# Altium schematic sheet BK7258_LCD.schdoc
size 335 x 193 mm
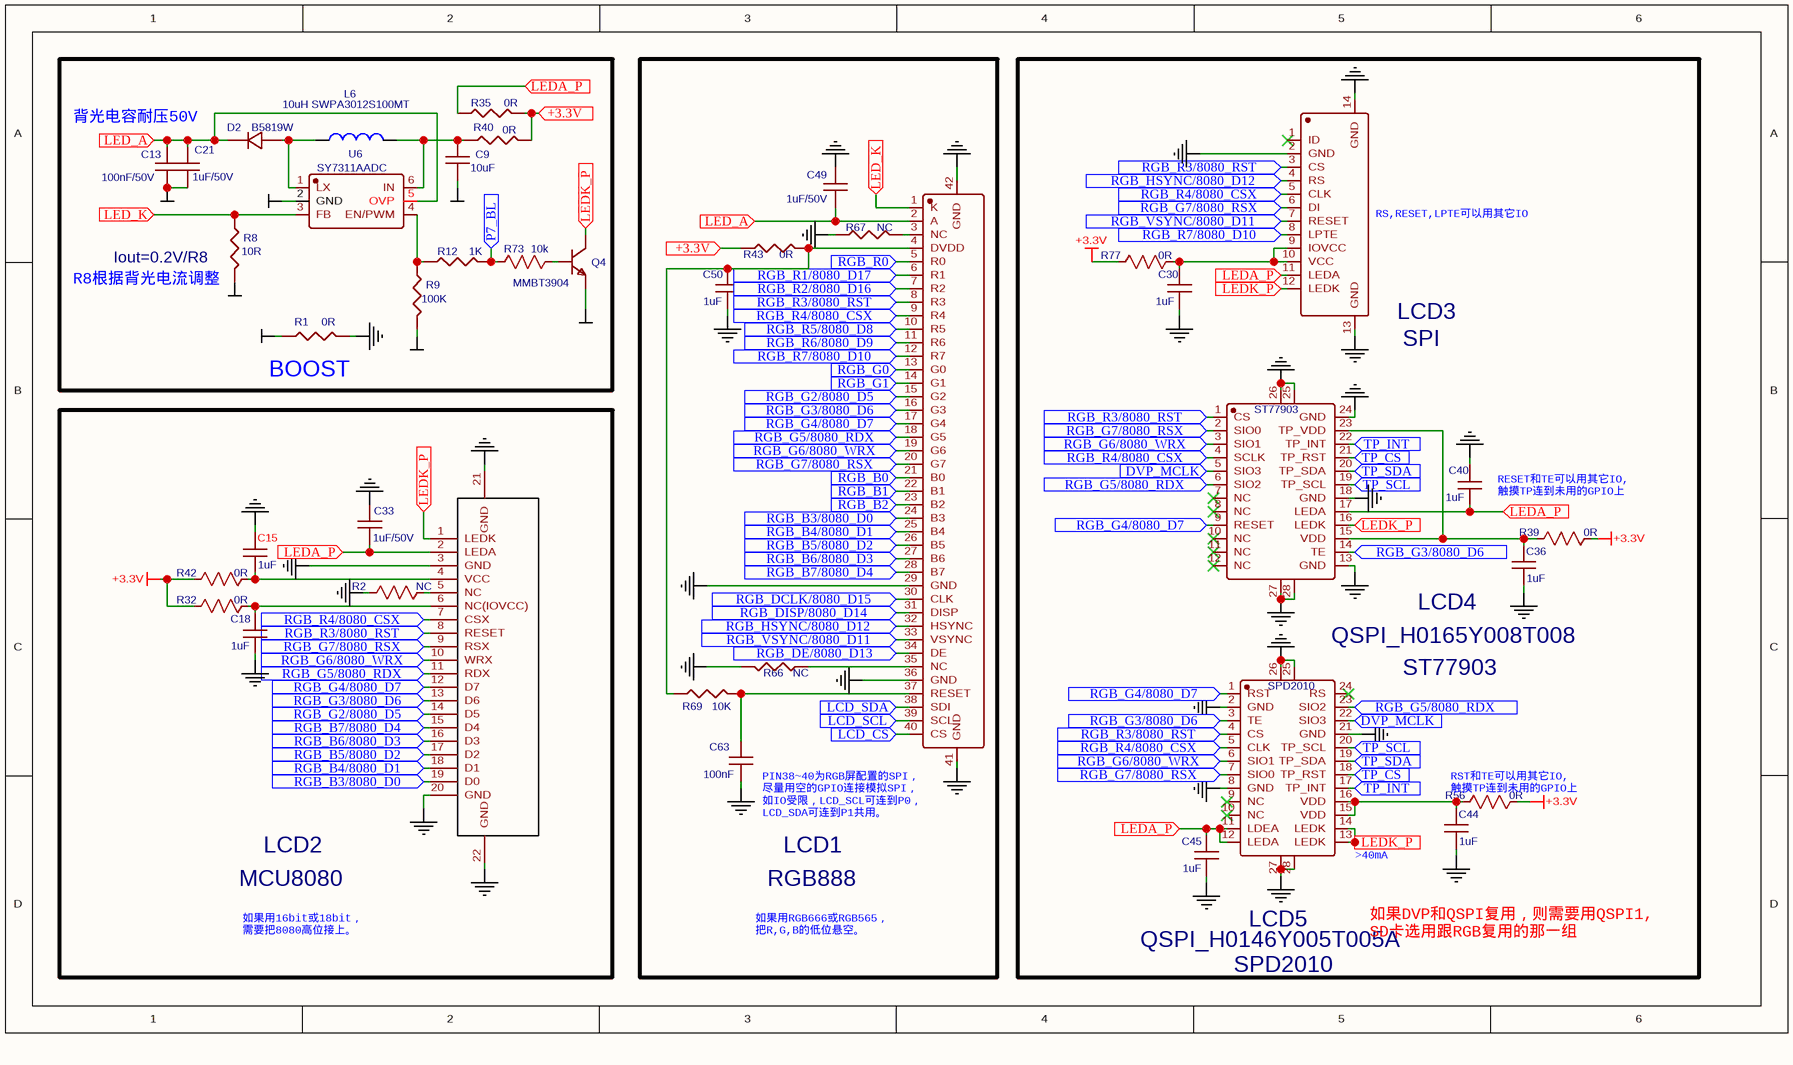
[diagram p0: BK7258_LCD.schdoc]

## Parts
C9  10uF  [C0603]
C13  100nF/50V  [C0603]
C15  1uF  [C0402]
C18  1uF  [C0402]
C21  1uF/50V  [C0603]
C30  1uF  [C0402]
C33  1uF/50V  [C0603]
C36  1uF  [C0402]
C40  1uF  [C0402]
C44  1uF  [C0402]
C45  1uF  [C0402]
C49  1uF/50V  [C0603]
C50  1uF  [C0402]
C63  100nF  [C0402]
D2  B5819W  [SOD-123]
L6  10uH SWPA3012S100MT  [L3012]
LCD1  RGB888  [FPC_0.5MM_40PIN_UPDATED2]
LCD2  MCU8080  [FPC_0.5MM_20PIN_UPDATED2]
LCD3  SPI  [FPC14PIN-0.5MM_UPDATED]
LCD4  QSPI_H0165Y008T008  [CONN-SMD_24P-P0.40_OK-14F024-04]
LCD5  QSPI_H0146Y005T005A  [CONN-SMD_24P-P0.40_OK-14F024-04]
Q4  MMBT3904  [SOT-23]
R1  0R  [R0402]
R2  NC  [R0402]
R8  10R  [R0402]
R9  100K  [R0402]
R12  1K  [R0402]
R32  0R  [R0402]
R35  0R  [R0402]
R39  0R  [R0402]
R40  0R  [R0402]
R42  0R  [R0402]
R43  0R  [R0402]
R56  0R  [R0402]
R66  NC  [R0201]
R67  NC  [R0402]
R69  10K  [R0402]
R73  10k  [R0402]
R77  0R  [R0402]
U6  SY7311AADC  [TSOT-23-6_L2.9-W1.6-P0.95-LS2.8-BR]

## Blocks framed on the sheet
BOOST: C9 C13 C21 D2 L6 Q4 R1 R8 R9 R12 R35 R40 R73 U6

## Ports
+3.3V (in), DVP_MCLK (in), LCD_CS (in), LCD_SCL (in), LCD_SDA (in), LED_A (in), LED_K (in), LEDA_P (in), LEDK_P (in), P7_BL (in), RGB_B0 (in), RGB_B1 (in), RGB_B2 (in), RGB_B3/8080_D0 (in), RGB_B4/8080_D1 (in), RGB_B5/8080_D2 (in), RGB_B6/8080_D3 (in), RGB_B7/8080_D4 (in), RGB_DCLK/8080_D15 (in), RGB_DE/8080_D13 (in), RGB_DISP/8080_D14 (in), RGB_G0 (in), RGB_G1 (in), RGB_G2/8080_D5 (in), RGB_G3/8080_D6 (in), RGB_G4/8080_D7 (in), RGB_G5/8080_RDX (in), RGB_G6/8080_WRX (in), RGB_G7/8080_RSX (in), RGB_HSYNC/8080_D12 (in), RGB_R0 (in), RGB_R1/8080_D17 (in), RGB_R2/8080_D16 (in), RGB_R3/8080_RST (in), RGB_R4/8080_CSX (in), RGB_R5/8080_D8 (in), RGB_R6/8080_D9 (in), RGB_R7/8080_D10 (in), RGB_VSYNC/8080_D11 (in), TP_CS (in), TP_INT (in), TP_SCL (in), TP_SDA (in)

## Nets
+3.3V: R32.1 R39.2 R42.1 R56.2 R77.1
GGND: C15.2 C18.1 C30.2 C33.1 C36.2 C40.2 C44.2 C45.2 C49.1 C50.2 C63.2 LCD1.29(GND) LCD1.36(GND) LCD1.41(GND) LCD1.42(GND) LCD2.3(GND) LCD2.20(GND) LCD2.21(GND) LCD2.22(GND) LCD3.2(GND) LCD3.13(GND) LCD3.14(GND) LCD4.13(GND) LCD4.18(GND) LCD4.24(GND) LCD4.25 LCD4.26 LCD4.27 LCD4.28 LCD5.2(GND) LCD5.8(GND) LCD5.21(GND) LCD5.25 LCD5.26 LCD5.27 LCD5.28 R1.2 R2.1 R66.2 R67.2
GND: C9.2 C13.2 C21.2 Q4.2(E) R1.1 R8.2 R9.2 U6.2(GND)
+3.3V: R35.2 R40.2 R43.2 ; port +3.3V  [a separate net that carries the same name]
DVP_MCLK: LCD4.5(SIO3) LCD5.22(SIO3) ; port DVP_MCLK
LCD_CS: LCD1.40(CS) ; port LCD_CS
LCD_SCL: LCD1.39(SCL) ; port LCD_SCL
LCD_SDA: LCD1.38(SDI) ; port LCD_SDA
LED_A: C13.1 C21.1 C49.2 D2.1(K) LCD1.2(A) U6.5(OVP) ; port LED_A
LED_K: LCD1.1(K) R8.1 U6.3(FB) ; port LED_K
LEDA_P: C33.2 C40.1 C45.1 LCD2.2(LEDA) LCD3.11(LEDA) LCD4.17(LEDA) LCD5.11(LDEA) LCD5.12(LEDA) R35.1 ; port LEDA_P
LEDK_P: LCD2.1(LEDK) LCD3.12(LEDK) LCD4.16(LEDK) LCD5.13(LEDK) LCD5.14(LEDK) Q4.3(C) ; port LEDK_P
P7_BL: R12.2 R73.1 ; port P7_BL
RGB_B0: LCD1.21(B0) ; port RGB_B0
RGB_B1: LCD1.22(B1) ; port RGB_B1
RGB_B2: LCD1.23(B2) ; port RGB_B2
RGB_B3/8080_D0: LCD1.24(B3) LCD2.19(D0) ; port RGB_B3/8080_D0
RGB_B4/8080_D1: LCD1.25(B4) LCD2.18(D1) ; port RGB_B4/8080_D1
RGB_B5/8080_D2: LCD1.26(B5) LCD2.17(D2) ; port RGB_B5/8080_D2
RGB_B6/8080_D3: LCD1.27(B6) LCD2.16(D3) ; port RGB_B6/8080_D3
RGB_B7/8080_D4: LCD1.28(B7) LCD2.15(D4) ; port RGB_B7/8080_D4
RGB_DCLK/8080_D15: LCD1.30(CLK) ; port RGB_DCLK/8080_D15
RGB_DE/8080_D13: LCD1.34(DE) ; port RGB_DE/8080_D13
RGB_DISP/8080_D14: LCD1.31(DISP) ; port RGB_DISP/8080_D14
RGB_G0: LCD1.13(G0) ; port RGB_G0
RGB_G1: LCD1.14(G1) ; port RGB_G1
RGB_G2/8080_D5: LCD1.15(G2) LCD2.14(D5) ; port RGB_G2/8080_D5
RGB_G3/8080_D6: LCD1.16(G3) LCD2.13(D6) LCD4.14(TE) LCD5.3(TE) ; port RGB_G3/8080_D6
RGB_G4/8080_D7: LCD1.17(G4) LCD2.12(D7) LCD4.9(RESET) LCD5.1(RST) ; port RGB_G4/8080_D7
RGB_G5/8080_RDX: LCD1.18(G5) LCD2.11(RDX) LCD4.6(SIO2) LCD5.23(SIO2) ; port RGB_G5/8080_RDX
RGB_G6/8080_WRX: LCD1.19(G6) LCD2.10(WRX) LCD4.3(SIO1) LCD5.6(SIO1) ; port RGB_G6/8080_WRX
RGB_G7/8080_RSX: LCD1.20(G7) LCD2.9(RSX) LCD3.6(DI) LCD4.2(SIO0) LCD5.7(SIO0) ; port RGB_G7/8080_RSX
RGB_HSYNC/8080_D12: LCD1.32(HSYNC) LCD3.4(RS) ; port RGB_HSYNC/8080_D12
RGB_R0: LCD1.5(R0) ; port RGB_R0
RGB_R1/8080_D17: LCD1.6(R1) ; port RGB_R1/8080_D17
RGB_R2/8080_D16: LCD1.7(R2) ; port RGB_R2/8080_D16
RGB_R3/8080_RST: LCD1.8(R3) LCD2.8(RESET) LCD3.3(CS) LCD4.1(CS) LCD5.4(CS) ; port RGB_R3/8080_RST
RGB_R4/8080_CSX: LCD1.9(R4) LCD2.7(CSX) LCD3.5(CLK) LCD4.4(SCLK) LCD5.5(CLK) ; port RGB_R4/8080_CSX
RGB_R5/8080_D8: LCD1.10(R5) ; port RGB_R5/8080_D8
RGB_R6/8080_D9: LCD1.11(R6) ; port RGB_R6/8080_D9
RGB_R7/8080_D10: LCD1.12(R7) LCD3.8(LPTE) ; port RGB_R7/8080_D10
RGB_VSYNC/8080_D11: LCD1.33(VSYNC) LCD3.7(RESET) ; port RGB_VSYNC/8080_D11
TP_CS: LCD4.21(TP_RST) LCD5.18(TP_RST) ; port TP_CS
TP_INT: LCD4.22(TP_INT) LCD5.17(TP_INT) ; port TP_INT
TP_SCL: LCD4.19(TP_SCL) LCD5.20(TP_SCL) ; port TP_SCL
TP_SDA: LCD4.20(TP_SDA) LCD5.19(TP_SDA) ; port TP_SDA
NetC9_1: C9.1 L6.2 R40.1 U6.6(IN)
NetC15_1: C15.1 LCD2.4(VCC) R42.2
NetC18_2: C18.2 LCD2.6(NC(IOVCC)) R32.2
NetC30_1: C30.1 LCD3.9(IOVCC) LCD3.10(VCC) R77.2
NetC36_1: C36.1 LCD4.15(VDD) LCD4.23(TP_VDD) R39.1
NetC44_1: C44.1 LCD5.15(VDD) LCD5.16(VDD) R56.1
NetC50_1: C50.1 LCD1.4(DVDD) R43.1 R69.2
NetC63_1: C63.1 LCD1.37(RESET) R69.1
NetD2_2: D2.2(A) L6.1 U6.1(LX)
NetLCD1_3: LCD1.3(NC) R67.1
NetLCD1_35: LCD1.35(NC) R66.1
NetLCD2_5: LCD2.5(NC) R2.2
NetQ4_1: Q4.1(B) R73.2
NetR9_1: R9.1 R12.1 U6.4(EN/PWM)

Not connected (* = marked no-connect by the designer): LCD3 1(ID)*; LCD4 7(NC)* 8(NC)* 10(NC)* 11(NC)* 12(NC)*; LCD5 9(NC)* 10(NC)* 24(RS)*

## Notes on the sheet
- 背光电容耐压50V
- (near LCD3) RS,RESET,LPTE可以用其它IO
- R8根据背光电流调整
- (near R8) Iout=0.2V/R8
- RESET和TE可以用其它IO,
  触摸TP连到未用的GPIO上
- ST77903
- PIN38~40为RGB屏配置的SPI，
  尽量用空的GPIO连接模拟SPI，
  如IO受限，LCD_SCL可连到P0，
  LCD_SDA可连到P1共用。
- RST和TE可以用其它IO,
  触摸TP连到未用的GPIO上
- (near LCD5) >40mA
- 如果用16bit或18bit，
  需要把8080高位接上。
- 如果用RGB666或RGB565，
  把R,G,B的低位悬空。
- 如果DVP和QSPI复用，则需要用QSPI1,
  SD卡选用跟RGB复用的那一组
- SPD2010

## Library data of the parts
C9 = 10uF: Manufacturer Part Number: 06035A101KAT2A; Manufacturer: AVX; APN: C029-0
C13 = 100nF/50V: Manufacturer Part Number: 06035A101KAT2A; Manufacturer: AVX; APN: C029-0
C15 C18 C30 C36 C40 C44 C45 C50 = 1uF: Manufacturer Part Number: 06035C103KAt2A; Manufacturer: AVX; APN: C006-0
C21 = 1uF/50V: Manufacturer Part Number: 06035A101KAT2A; Manufacturer: AVX; APN: C029-0
C33 C49 = 1uF/50V: Manufacturer Part Number: 06035C103KAt2A; Manufacturer: AVX; APN: C006-0
C63 = 100nF: Manufacturer Part Number: 06035C103KAt2A; Manufacturer: AVX; APN: C006-0
D2 = B5819W: Manufacturer: DIODES; Manufacturer Part: 1N5819HW1-7-F; Contributor: LCSC
L6 = 10uH SWPA3012S100MT: Manufacturer Part Number: 0805HS-030TMBC; Manufacturer: COILCRAFT; APN: L035-0
LCD1 = RGB888: Contributor: guogen.le
LCD2 = MCU8080: BOM_Manufacturer: JS(钜硕电子); BOM_Manufacturer Part: AFC01-S20FCA-00; Contributor: guogen.le
LCD3 = SPI: BOM_Manufacturer: HDGC（华德共创）; BOM_Manufacturer Part: 0.5K-1.5-12PWB; Contributor: jian.shi1
LCD4 = QSPI_H0165Y008T008: BOM_Manufacturer: YXT(益鑫通); BOM_Manufacturer Part: YXT-BB10-24S-02; Contributor: qunshan.xu
LCD5 = QSPI_H0146Y005T005A: BOM_Manufacturer: YXT(益鑫通); BOM_Manufacturer Part: YXT-BB10-24S-02; Contributor: qunshan.xu
Q4 = MMBT3904: BOM_Manufacturer: GOODWORK; Contributor: lcsc
R1 R35 R40 = 0R: Manufacturer Part Number: RK73H2AT4752F; Manufacturer: KOA; APN: R096-0
R2 = NC: nameAlias: Value(Ω); Contributor: LCEDA_Lib
R8 = 10R: Manufacturer Part Number: RK73H2AT4752F; Manufacturer: KOA; APN: R096-0
R9 = 100K: Manufacturer Part Number: RK73H2AT4752F; Manufacturer: KOA; APN: R096-0
R12 = 1K: Manufacturer Part Number: RK73H2AT4752F; Manufacturer: KOA; APN: R096-0
R32 R39 R42 R56 R77 = 0R: nameAlias: Value(Ω); Contributor: LCEDA_Lib
R43 = 0R: Manufacturer Part Number: RM73B1JT240J; Manufacturer: KOA; APN: R125-0
R66 = NC: Manufacturer Part Number: RK73H2AT4752F; Manufacturer: KOA; APN: R096-0
R67 = NC: Manufacturer Part Number: RM73B1JT240J; Manufacturer: KOA; APN: R125-0
R69 = 10K: Manufacturer Part Number: RM73B1JT240J; Manufacturer: KOA; APN: R125-0
R73 = 10k: nameAlias: Value(Ω); Contributor: LCEDA_Lib
U6 = SY7311AADC: Manufacturer: 矽力杰silergy; Contributor: lcsc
